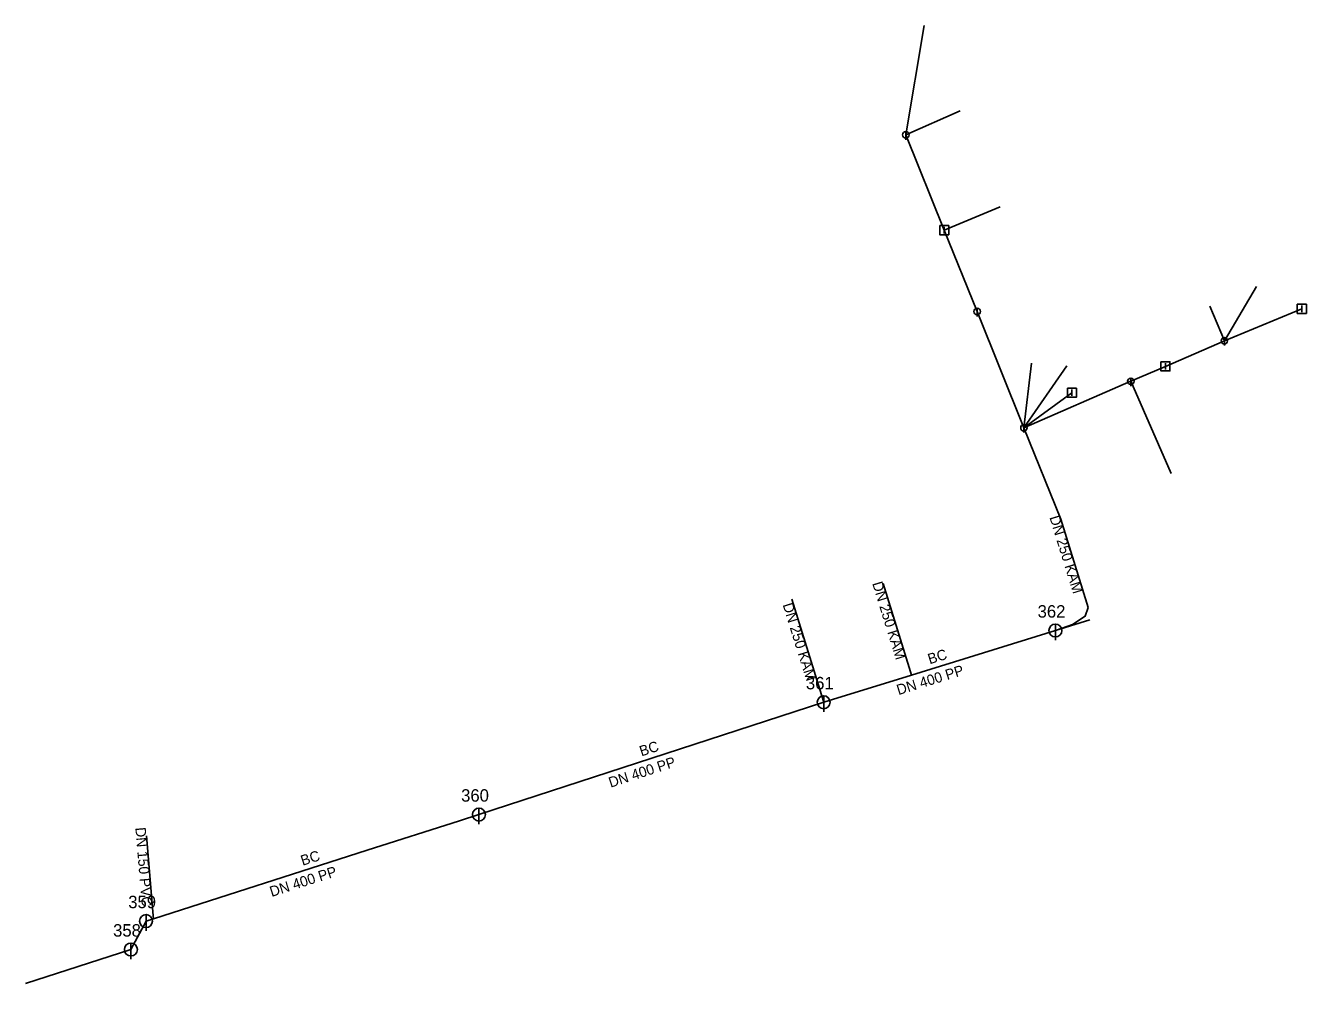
# Model space of a CAD drawing. Extents: x -491015 to -490621, y -1125687 to -1125202.
# Drawn here: x -490819.5 to -490621.4, y -1125687.5 to -1125539.3 of the extents above; entities that cross this region are included whole.
import ezdxf

# ---------------------------------------------------------------- set-up
doc = ezdxf.new("R2010")
doc.units = 0
for name, color, linetype in [('_pripojka_kanal_destova_prevzato_z_dokumentace_', 7, 'Continuous'), ('_pripojka_kanal_destova_priblizne_', 7, 'Continuous'), ('_pripojka_kanal_jednotna_prevzato_z_dokumentace_', 7, 'Continuous'), ('_pripojka_kanal_jednotna_priblizne_', 7, 'Continuous'), ('_pripojka_kanal_splaskova_priblizne_', 7, 'Continuous'), ('_stoka_jednotna_smvak_prevzato_z_dokumentace_', 7, 'Continuous'), ('Default', 7, 'Continuous'), ('MoLevel 119', 7, 'Continuous'), ('MoLevel 120', 7, 'Continuous'), ('MoLevel 126', 7, 'Continuous'), ('MoLevel 130', 7, 'Continuous'), ('MoLevel 57', 7, 'Continuous'), ('MoLevel 63', 7, 'Continuous'), ('MoLevel 68', 7, 'Continuous'), ('MoLevel 69', 7, 'Continuous')]:
    doc.layers.add(name, color=color, linetype=linetype)

# ---------------------------------------------------------------- blocks, each defined once
blk = doc.blocks.new('_vpust_')
at = {"layer": 'Default'}
blk.add_line((0, 0.025), (0, -0.025), dxfattribs=at)
blk.add_lwpolyline([(-0.035, 0.035), (0.035, 0.035), (0.035, -0.035), (-0.035, -0.035), (-0.035, 0.035)], dxfattribs=at)
blk = doc.blocks.new('_sachta_kanal_prip_')
at = {"layer": 'Default'}
blk.add_line((0, 0.05), (0, -0.075), dxfattribs=at)
blk.add_circle((0, 0), 0.05, dxfattribs=at)
blk = doc.blocks.new('_sachta_kanal_prevzato_z_dokumentace_')
at = {"layer": 'Default'}
blk.add_line((0, 0.05), (0, -0.075), dxfattribs=at)
blk.add_circle((0, 0), 0.05, dxfattribs=at)

msp = doc.modelspace()

# ---------------------------------------------------------------- linework, layer by layer
at = {"layer": '_pripojka_kanal_destova_prevzato_z_dokumentace_'}
msp.add_lwpolyline([(-490800.85, -1125664.66), (-490799.81, -1125676.97), (-490799.77, -1125677.48)], dxfattribs=at)
at = {"layer": '_pripojka_kanal_destova_priblizne_'}
for p, q in [((-490680.55, -1125539.29), (-490683.38, -1125556.19)), ((-490668.77, -1125567.32), (-490677.44, -1125570.94)), ((-490629.14, -1125579.66), (-490634.12, -1125588.06)), ((-490622.13, -1125583.11), (-490634.12, -1125588.06)), ((-490663.94, -1125591.53), (-490665.12, -1125601.51)), ((-490658.47, -1125591.94), (-490665.12, -1125601.51)), ((-490657.7, -1125596.09), (-490665.12, -1125601.51))]:
    msp.add_line(p, q, dxfattribs=at)
at = {"layer": '_pripojka_kanal_jednotna_prevzato_z_dokumentace_'}
for p, q in [((-490659.42, -1125615.64), (-490655.18, -1125629.34)), ((-490654.9, -1125631.23), (-490660.25, -1125632.89))]:
    msp.add_line(p, q, dxfattribs=at)
for points in [[(-490686.91, -1125625.63), (-490682.68, -1125639.26), (-490682.52, -1125639.79)], [(-490701.04, -1125628.02), (-490696.44, -1125642.84), (-490696.09, -1125643.99)], [(-490655.18, -1125629.34), (-490655.64, -1125630.68), (-490657.62, -1125631.97), (-490660.25, -1125632.89)]]:
    msp.add_lwpolyline(points, dxfattribs=at)
at = {"layer": '_pripojka_kanal_jednotna_priblizne_'}
for p, q in [((-490683.38, -1125556.19), (-490677.44, -1125570.94)), ((-490677.44, -1125570.94), (-490672.36, -1125583.53)), ((-490672.36, -1125583.53), (-490665.12, -1125601.51)), ((-490634.12, -1125588.06), (-490643.23, -1125592.01)), ((-490643.23, -1125592.01), (-490648.58, -1125594.33)), ((-490648.58, -1125594.33), (-490665.12, -1125601.51)), ((-490665.12, -1125601.51), (-490659.42, -1125615.64))]:
    msp.add_line(p, q, dxfattribs=at)
at = {"layer": '_pripojka_kanal_splaskova_priblizne_'}
for p, q in [((-490675, -1125552.5), (-490683.38, -1125556.19)), ((-490636.38, -1125582.69), (-490634.12, -1125588.06)), ((-490642.32, -1125608.57), (-490648.58, -1125594.33))]:
    msp.add_line(p, q, dxfattribs=at)
at = {"layer": '_stoka_jednotna_smvak_prevzato_z_dokumentace_'}
for p, q in [((-490696.09, -1125643.99), (-490749.42, -1125661.37)), ((-490800.91, -1125677.85), (-490803.25, -1125682.25)), ((-490803.25, -1125682.25), (-490819.53, -1125687.49))]:
    msp.add_line(p, q, dxfattribs=at)
for points in [[(-490660.25, -1125632.89), (-490682.52, -1125639.79), (-490696.09, -1125643.99)], [(-490749.42, -1125661.37), (-490752.44, -1125662.34), (-490766.69, -1125666.9), (-490799.77, -1125677.48), (-490800.91, -1125677.85)]]:
    msp.add_lwpolyline(points, dxfattribs=at)

# ---------------------------------------------------------------- block references
at = {"layer": 'MoLevel 119', "xscale": 20, "yscale": 20}
for p in [(-490660.25, -1125632.89), (-490696.09, -1125643.99), (-490749.42, -1125661.37), (-490800.91, -1125677.85), (-490803.25, -1125682.25)]:
    msp.add_blockref('_sachta_kanal_prevzato_z_dokumentace_', p, dxfattribs=at)
at = {"layer": 'MoLevel 57', "xscale": 10, "yscale": 10}
for p in [(-490683.38, -1125556.19), (-490672.36, -1125583.53), (-490634.12, -1125588.06), (-490648.58, -1125594.33), (-490665.12, -1125601.51)]:
    msp.add_blockref('_sachta_kanal_prip_', p, dxfattribs=at)
at = {"layer": 'MoLevel 63', "xscale": 20, "yscale": 20}
for p in [(-490677.44, -1125570.94), (-490622.13, -1125583.11), (-490643.23, -1125592.01), (-490657.7, -1125596.09)]:
    msp.add_blockref('_vpust_', p, dxfattribs=at)

# ---------------------------------------------------------------- texts
at = {"layer": 'MoLevel 120'}
for s, p in [('362', (-490663, -1125630.89)), ('361', (-490698.84, -1125641.99)), ('360', (-490752.17, -1125659.37)), ('359', (-490803.66, -1125675.85)), ('358', (-490806, -1125680.25))]:
    msp.add_text(s, height=1.926, dxfattribs=at).set_placement(p)
at = {"layer": 'MoLevel 126'}
for rotation, p in [(287.2091, (-490661.19, -1125615.37)), (287.2214, (-490688.6, -1125625.59)), (287.2287, (-490702.45, -1125628.89))]:
    msp.add_text('DN 250 KAM', height=1.605, rotation=rotation, dxfattribs=at).set_placement(p)
at = {"layer": 'MoLevel 130'}
msp.add_text('DN 150 PVC', height=1.605, rotation=274.8291, dxfattribs=at).set_placement((-490802.57, -1125663.4))
at = {"layer": 'MoLevel 68'}
for rotation, p in [(17.2148, (-490684.52, -1125642.89)), (18.0506, (-490729.05, -1125657.22)), (17.7359, (-490781.48, -1125674.12))]:
    msp.add_text('DN 400 PP', height=1.605, rotation=rotation, dxfattribs=at).set_placement(p)
at = {"layer": 'MoLevel 69'}
for rotation, p in [(17.2148, (-490679.7, -1125638.12)), (18.0506, (-490724.28, -1125652.38)), (17.7359, (-490776.69, -1125669.3))]:
    msp.add_text('BC', height=1.605, rotation=rotation, dxfattribs=at).set_placement(p)

doc.saveas('drawing.dxf')
